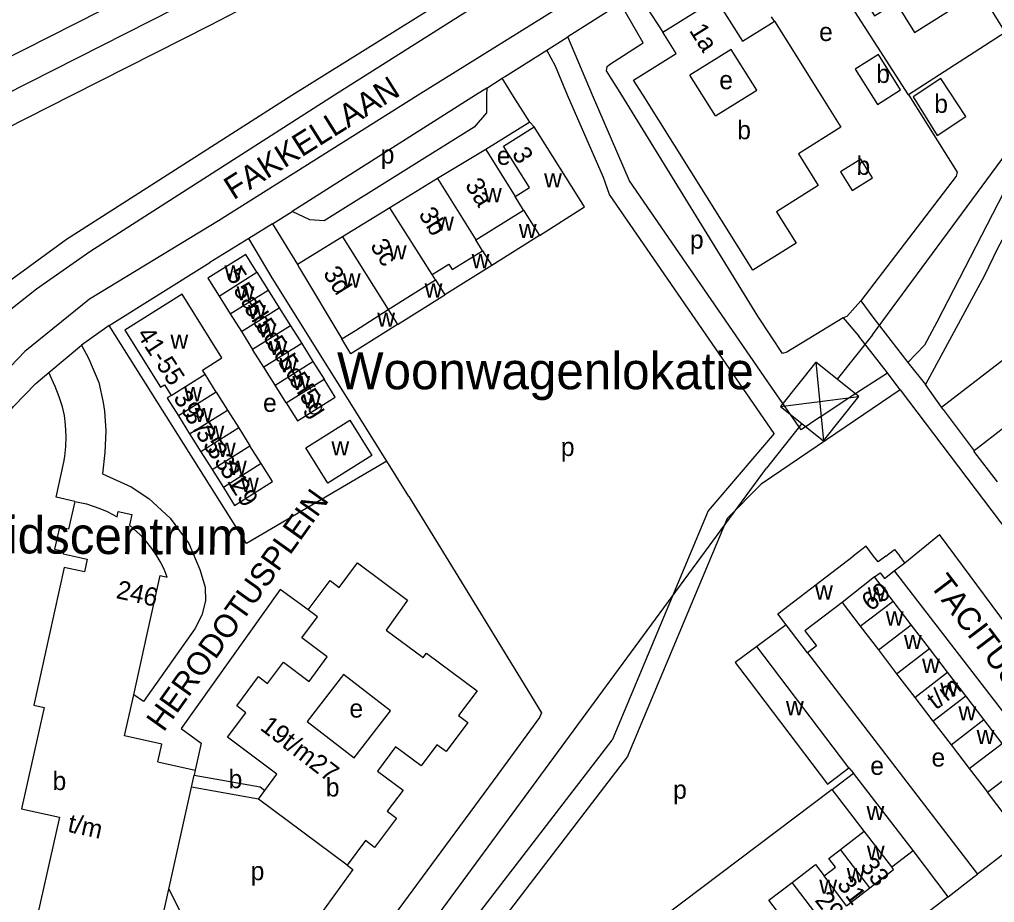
# Model space of a CAD drawing. Extents: x 158848 to 160613, y 385889 to 387762.
# Drawn here: x 159660 to 159871.5, y 386924.8 to 387116.4 of the extents above; entities that cross this region are included whole.
import ezdxf

# ---------------------------------------------------------------- set-up
doc = ezdxf.new("R2010")
doc.units = 0
for name, color, linetype in [('BLT_Basislijn', 7, 'Continuous'), ('BLT_Bebouwing', 7, 'Continuous'), ('BLT_Bebouwing_beschrifting', 7, 'Continuous'), ('BLT_Centroide', 7, 'Continuous'), ('BLT_Hoogspanningsmast_en_leidingen', 7, 'Continuous'), ('BLT_Huisnummer', 7, 'Continuous'), ('BLT_Huisnummer_ tussenligend', 7, 'Continuous'), ('BLT_Huisnummer_reeks', 7, 'Continuous'), ('BLT_Onderdoorgang_en_onderverdeling', 7, 'Continuous'), ('BLT_Onderverdeling_panden', 7, 'Continuous'), ('BLT_Straatnaam', 7, 'Continuous'), ('BLT_Terrein_beschrifting', 7, 'Continuous')]:
    doc.layers.add(name, color=color, linetype=linetype)

msp = doc.modelspace()

# ---------------------------------------------------------------- linework, layer by layer
at = {"layer": 'BLT_Basislijn'}
for p, q in [((159852.89, 387100.09), (159825.6, 387142.4)), ((159712.26, 387135.93), (159645.73, 387102.09)), ((159793.99, 387122.27), (159799.55, 387113.71)), ((159790.39, 387119.92), (159778.96, 387112.63)), ((159823.79, 387116.06), (159823.15, 387117.04)), ((159774.45, 387109.79), (159778.96, 387112.63)), ((159765.24, 387103.99), (159774.45, 387109.79)), ((159764.75, 387103.67), (159765.24, 387103.99)), ((159761.41, 387101.56), (159764.75, 387103.67)), ((159860.03, 387032.3), (159948.85, 387100.76)), ((159770.74, 387094.18), (159761.16, 387088.19)), ((159771.67, 387093.14), (159770.74, 387094.18)), ((159761.16, 387088.19), (159750.72, 387081.9)), ((159761.16, 387088.19), (159767.57, 387078.01)), ((159750.72, 387081.9), (159740.39, 387075.56)), ((159750.72, 387081.9), (159759, 387068.61)), ((159714.94, 387072.09), (159719.21, 387074.74)), ((159740.39, 387075.56), (159730.07, 387069.24)), ((159749.57, 387061.1), (159740.39, 387075.56)), ((159714.94, 387072.09), (159709.75, 387068.91)), ((159714.94, 387072.09), (159720.3, 387063.25)), ((159709.75, 387068.91), (159701.35, 387063.73)), ((159714.86, 387060.35), (159709.75, 387068.91)), ((159730.07, 387069.24), (159720.3, 387063.25)), ((159730.07, 387069.24), (159740.02, 387053.5)), ((159679.48, 387050.06), (159701.35, 387063.73)), ((159720.3, 387063.25), (159720.77, 387062.48)), ((159720.77, 387062.48), (159729.93, 387047.15)), ((159739.73, 387020.59), (159714.86, 387060.35)), ((159842.56, 387055.35), (159845.32, 387051.54)), ((159838.67, 387051.69), (159842.07, 387047.7)), ((159845.32, 387051.54), (159852.75, 387041.99)), ((159679.48, 387050.06), (159673.48, 387045.79)), ((159848.29, 387039.75), (159842.07, 387047.7)), ((159852.75, 387041.99), (159856.52, 387037.21)), ((159851.06, 387036.1), (159848.29, 387039.75)), ((159829.55, 387027.36), (159823.15, 387036.66)), ((159851.06, 387036.1), (159823.15, 387017.12)), ((159851.06, 387036.1), (159877.63, 387000.96)), ((159860.03, 387032.3), (159856.52, 387037.21)), ((159860.38, 387031.82), (159860.03, 387032.3)), ((159860.38, 387031.82), (159867.1, 387022.85)), ((159833.61, 387030.17), (159829.55, 387027.36)), ((159744.51, 387012.95), (159739.73, 387020.59)), ((159744.51, 387012.95), (159753.13, 386998.85)), ((159852.08, 386998.53), (159859.57, 387004.69)), ((159753.13, 386998.85), (159761.37, 386985.36)), ((159849.79, 386996.78), (159888.25, 386946.8)), ((159761.37, 386985.36), (159762.96, 386982.75)), ((159826.35, 386985.09), (159819.96, 386980.42)), ((159830.99, 386979.03), (159867.81, 386931)), ((159839.95, 386954.06), (159840.95, 386952.9)), ((159888.25, 386946.8), (159867.81, 386931)), ((159861.44, 386926.05), (159853.86, 386936.11)), ((159692.41, 386927.7), (159709.34, 386894.68))]:
    msp.add_line(p, q, dxfattribs=at)
for points in [[(159910.62, 387195.56), (159926.67, 387162.23), (159927.14, 387160.7), (159900.93, 387130.86), (159900.07, 387130.23), (159884.36, 387100), (159859.01, 387050.73), (159856.32, 387045.74), (159852.75, 387041.99)], [(159823.15, 387177.85), (159809.32, 387170.86), (159746.21, 387138.49), (159701.32, 387115.11), (159671.47, 387100), (159559.25, 387043.07), (159557.97, 387041.11), (159558.04, 387038.5), (159580.37, 386992.95), (159585.56, 386982.75)], [(159623.71, 387015.42), (159631.38, 387030.86), (159637.32, 387039.39), (159645.79, 387049.2), (159657.37, 387059.37), (159670.23, 387068.78), (159719.14, 387100), (159823.15, 387164.91)], [(159823.15, 387159.28), (159773.42, 387128.16), (159760.94, 387120.62), (159728.37, 387100), (159675.31, 387066.01), (159663.73, 387057.91), (159654.6, 387050.75), (159646.07, 387041.94), (159637.74, 387030.32), (159619.36, 386994.41)], [(159945.27, 387143.28), (159931.76, 387155.39), (159930.71, 387156.05), (159923.76, 387148.68), (159904.06, 387126.47), (159890.19, 387100), (159872.2, 387066.71), (159869.35, 387060.89), (159856.52, 387037.21)], [(159823.15, 387147.72), (159746.52, 387100), (159703.19, 387072.74), (159675.19, 387055.74), (159661.19, 387044.39), (159651.8, 387034.62), (159642.89, 387021.89), (159640.19, 387017.12), (159625.68, 386986.72)], [(159715.29, 387129.57), (159698.9, 387121.52), (159656.71, 387100), (159649.19, 387096.1)], [(159868.37, 387122.56), (159873.87, 387113.59), (159852.89, 387100.09)], [(159823.15, 387047.57), (159820.21, 387052.05), (159790.68, 387100), (159787.37, 387105.28), (159787.5, 387106.21), (159788.04, 387106.69), (159795.3, 387111.34), (159790.39, 387119.92)], [(159823.15, 387036.66), (159792.37, 387081.45), (159784.33, 387100), (159778.96, 387112.63)], [(159823.76, 387026.61), (159787.99, 387078.48), (159786.68, 387082.11), (159778.92, 387100), (159776.29, 387106.32), (159774.45, 387109.79)], [(159770.74, 387094.18), (159767.17, 387099.69), (159764.75, 387103.67)], [(159761.41, 387101.56), (159758.95, 387100), (159719.21, 387074.74)], [(159761.41, 387101.56), (159761.35, 387100), (159761.31, 387096.17), (159758.69, 387093.1), (159726.09, 387072.77), (159723, 387072.96), (159719.21, 387074.74)], [(159852.89, 387100.09), (159852.94, 387100), (159863.41, 387083.3), (159863.2, 387082.45), (159842.56, 387055.35)], [(159842.56, 387055.35), (159839.46, 387051.95), (159838.67, 387051.69)], [(159838.67, 387051.69), (159826.47, 387044.23), (159825.52, 387043.97), (159823.15, 387047.57)], [(159739.73, 387020.59), (159709.25, 387002.72), (159679.48, 387050.06)], [(159666.38, 387039.82), (159673.48, 387045.79)], [(159673.48, 387045.79), (159675.01, 387042.97), (159677.23, 387037.69), (159678.18, 387033.36), (159678.48, 387031.47), (159678.76, 387027.2), (159678.51, 387022.48), (159678.04, 387017.84), (159684.23, 387015.05), (159688.08, 387012.49), (159692.71, 387008.24), (159696.75, 387002.75), (159699.16, 386997.08), (159700.33, 386993.29), (159700.36, 386990.32), (159699.59, 386987.19), (159698.05, 386984.22), (159686.94, 386968.43), (159684.82, 386969.9)], [(159653.09, 387025.66), (159658.73, 387032.44), (159663.57, 387037.48), (159666.38, 387039.82)], [(159672.01, 387011.87), (159667.96, 387012.76), (159669.64, 387020.37), (159669.89, 387021.64), (159670.11, 387023.79), (159670.14, 387025.98), (159670.01, 387028.45), (159669.76, 387030.51), (159669.34, 387032.38), (159668.63, 387034.54), (159667.75, 387036.8), (159666.38, 387039.82)], [(159833.61, 387030.17), (159840.42, 387034.7), (159848.29, 387039.75)], [(159823.76, 387026.61), (159809.44, 387009.83), (159788.61, 386960.07)], [(159823.15, 387017.12), (159820.91, 387015.59), (159813.5, 387008.13)], [(159813.5, 387008.13), (159792.21, 386957.27), (159791.91, 386956.54), (159735.96, 386883.49), (159761.48, 386849.27)], [(159876.25, 386986.01), (159874.33, 386984.83), (159859.57, 387004.69)], [(159722.66, 386988.31), (159716.6, 386992.73), (159695.07, 386962.61), (159699.41, 386959.42), (159698.13, 386953.55)], [(159762.96, 386982.75), (159773.23, 386965.96), (159772.86, 386965), (159763.8, 386952.59), (159718.62, 386891.3)], [(159758.29, 386846.68), (159730.2, 386884.11), (159788.61, 386960.07)], [(159836.33, 386949.34), (159747.41, 386882.22), (159747.57, 386881.65), (159752.07, 386875.69)], [(159731.11, 386932.94), (159732.36, 386932.01), (159709.77, 386900.75), (159713.47, 386898.08)], [(159861.44, 386926.05), (159867.07, 386930.43), (159867.81, 386931)], [(159861.44, 386926.05), (159860.61, 386925.4), (159768.29, 386854.43)]]:
    msp.add_lwpolyline(points, dxfattribs=at)
at = {"layer": 'BLT_Bebouwing'}
for p, q in [((159823.15, 387115.66), (159823.79, 387116.06)), ((159814.4, 387109.92), (159805.44, 387104.35)), ((159765.05, 387088.96), (159771.67, 387093.14)), ((159782.6, 387075.78), (159771.67, 387093.14)), ((159770.69, 387079.98), (159765.05, 387088.96)), ((159767.57, 387078.01), (159770.69, 387079.98)), ((159769.34, 387075.06), (159767.57, 387078.01)), ((159759, 387068.61), (159769.34, 387075.06)), ((159772.84, 387069.55), (159782.6, 387075.78)), ((159760.47, 387066.26), (159759, 387068.61)), ((159772.84, 387069.55), (159762.48, 387063.06)), ((159711.53, 387061.59), (159713.96, 387057.72)), ((159762.48, 387063.06), (159752.32, 387056.7)), ((159740.02, 387053.5), (159750.27, 387059.95)), ((159750.27, 387059.95), (159749.57, 387061.1)), ((159713.96, 387057.72), (159716.39, 387053.85)), ((159703.31, 387056.43), (159705.74, 387052.56)), ((159742.03, 387050.25), (159752.32, 387056.7)), ((159716.39, 387053.85), (159718.82, 387049.98)), ((159705.74, 387052.56), (159708.17, 387048.7)), ((159708.17, 387048.7), (159710.6, 387044.83)), ((159718.82, 387049.98), (159721.24, 387046.11)), ((159713.03, 387040.96), (159710.6, 387044.83)), ((159721.24, 387046.11), (159723.68, 387042.24)), ((159715.46, 387037.09), (159713.03, 387040.96)), ((159723.68, 387042.24), (159726.1, 387038.38)), ((159702.71, 387035.57), (159700.28, 387039.46)), ((159717.89, 387033.22), (159715.46, 387037.09)), ((159702.71, 387035.57), (159705.15, 387031.69)), ((159694.49, 387030.41), (159696.93, 387026.53)), ((159705.15, 387031.69), (159707.59, 387027.8)), ((159707.59, 387027.8), (159710.02, 387023.92)), ((159873.87, 387028.04), (159867.1, 387022.85)), ((159712.43, 387020.07), (159710.02, 387023.92)), ((159699.38, 387022.64), (159701.82, 387018.76)), ((159701.82, 387018.76), (159704.26, 387014.88)), ((159849.79, 386996.78), (159852.08, 386998.53)), ((159852.08, 386998.53), (159850.96, 387000)), ((159849.52, 386990.25), (159845.52, 386995.48)), ((159838.45, 386989.93), (159842.39, 386984.79)), ((159853.46, 386985.1), (159849.52, 386990.25)), ((159830.99, 386979.03), (159826.35, 386985.09)), ((159842.39, 386984.79), (159846.33, 386979.64)), ((159857.41, 386979.96), (159853.46, 386985.1)), ((159839.95, 386954.06), (159819.96, 386980.42)), ((159846.33, 386979.64), (159850.27, 386974.49)), ((159861.35, 386974.81), (159857.41, 386979.96)), ((159865.29, 386969.66), (159861.35, 386974.81)), ((159730.28, 386974.28), (159722.41, 386964.08)), ((159740.48, 386966.41), (159730.28, 386974.28)), ((159850.27, 386974.49), (159854.22, 386969.35)), ((159854.22, 386969.35), (159858.16, 386964.2)), ((159869.23, 386964.52), (159865.29, 386969.66)), ((159732.61, 386956.22), (159740.48, 386966.41)), ((159858.16, 386964.2), (159862.1, 386959.05)), ((159873.17, 386959.37), (159869.23, 386964.52)), ((159722.41, 386964.08), (159732.61, 386956.22)), ((159862.1, 386959.05), (159866.04, 386953.91)), ((159853.86, 386936.11), (159840.95, 386952.9)), ((159843.26, 386940.33), (159836.33, 386949.34)), ((159849.23, 386932.55), (159853.86, 386936.11)), ((159839.45, 386924.15), (159844.5, 386928.03))]:
    msp.add_line(p, q, dxfattribs=at)
for points in [[(159843.38, 387130.8), (159845.13, 387127.97), (159840.59, 387125.12), (159845.52, 387117.21), (159850.12, 387120.08), (159854.18, 387113.62), (159868.37, 387122.56)], [(159799.55, 387113.71), (159811.09, 387120.94), (159816.87, 387111.72), (159823.15, 387115.66)], [(159823.79, 387116.06), (159826.45, 387111.82), (159833.85, 387100), (159838.21, 387093.04), (159828.99, 387087.26), (159833.3, 387080.38), (159824.24, 387074.71), (159828.5, 387067.91), (159823.32, 387064.67), (159823.15, 387064.56)], [(159823.15, 387064.56), (159819.08, 387062.01), (159795.28, 387100), (159793.23, 387103.27), (159802.47, 387109.05), (159799.55, 387113.71)], [(159810.97, 387095.52), (159819.96, 387101.1), (159814.4, 387109.92)], [(159810.97, 387095.52), (159805.44, 387104.35)], [(159838.09, 387083.38), (159840.65, 387079.3), (159845.08, 387082.08), (159842.52, 387086.15), (159838.09, 387083.38)], [(159749.57, 387061.1), (159753.17, 387063.35), (159753.92, 387062.16), (159760.47, 387066.26)], [(159711.53, 387061.59), (159709.1, 387065.46), (159700.89, 387060.3), (159703.31, 387056.43)], [(159700.28, 387039.46), (159699.71, 387040.37), (159703.91, 387043.03), (159695.3, 387056.8), (159682.85, 387048.99), (159690.62, 387036.62), (159691.49, 387037.18), (159691.49, 387037.18), (159692.95, 387034.86)], [(159729.93, 387047.15), (159732.88, 387048.98), (159740.02, 387053.5)], [(159742.03, 387050.25), (159731.93, 387043.92), (159729.93, 387047.15)], [(159717.89, 387033.22), (159720.32, 387029.35), (159728.53, 387034.51), (159726.1, 387038.38)], [(159692.95, 387034.86), (159692.06, 387034.3), (159694.49, 387030.41)], [(159696.93, 387026.53), (159696.93, 387026.53), (159699.38, 387022.64)], [(159867.1, 387022.85), (159867, 387022.77), (159872.1, 387016.13)], [(159704.26, 387014.88), (159706.7, 387010.99), (159714.89, 387016.15), (159712.43, 387020.07)], [(159672.01, 387011.87), (159670.67, 387005.81), (159668.7, 387006.24), (159667.64, 387001.48), (159669.62, 387001.06), (159669.49, 387000.51), (159674.71, 386999.37)], [(159672.01, 387011.87), (159674.54, 387011.31), (159677.46, 387010.35), (159679.02, 387009.67), (159681.21, 387008.53)], [(159681.21, 387008.53), (159681.45, 387009.68), (159684.4, 387009.03), (159683.87, 387006.69)], [(159690.56, 386995.8), (159692.1, 386995.46), (159691.42, 386997.13), (159690.57, 386998.82), (159689.85, 387000.03), (159688.76, 387001.68), (159687.36, 387003.39), (159686.24, 387004.59), (159683.87, 387006.69)], [(159845.28, 387000), (159843.66, 387002.12), (159840.9, 387000)], [(159847.93, 387000), (159849.84, 387001.46), (159850.96, 387000)], [(159674.71, 386999.37), (159674.16, 386996.57), (159669.71, 386997.5), (159666.47, 386982.78)], [(159727.39, 386994.67), (159729.37, 386993.2), (159733.35, 386998.51)], [(159733.35, 386998.51), (159744.21, 386990.44), (159739.59, 386983.96)], [(159826.35, 386985.09), (159824.53, 386987.47), (159840.9, 387000)], [(159847.93, 387000), (159846.26, 386998.72), (159845.28, 387000)], [(159845.52, 386995.48), (159846.7, 386996.38), (159847.65, 386995.14), (159849.79, 386996.78)], [(159687.67, 386982.75), (159690.56, 386995.8)], [(159722.66, 386988.31), (159727.39, 386994.67)], [(159838.45, 386989.93), (159830.41, 386983.77), (159832.91, 386980.5), (159830.99, 386979.03)], [(159724.67, 386986.8), (159722.66, 386988.31)], [(159726.79, 386978.14), (159721.26, 386982.24), (159724.67, 386986.8)], [(159739.59, 386983.96), (159747.59, 386978), (159748.3, 386978.95)], [(159666.47, 386982.78), (159663.11, 386967.63), (159665.4, 386967.12), (159660.47, 386945.2)], [(159684.82, 386969.9), (159687.67, 386982.75)], [(159748.3, 386978.95), (159759.29, 386970.76), (159755.28, 386965.45), (159757.28, 386963.93), (159752.55, 386957.57), (159750.59, 386959.05), (159747.16, 386954.51), (159741.61, 386958.62), (159737.66, 386953.35), (159743.23, 386949.21), (159739.81, 386944.63), (159741.8, 386943.15), (159737.05, 386936.79)], [(159819.96, 386980.42), (159815.3, 386976.88), (159818.32, 386972.9), (159835.3, 386950.53), (159835.97, 386951.04), (159839.95, 386954.06)], [(159711.89, 386973.86), (159713.86, 386972.39), (159717.3, 386976.96)], [(159717.3, 386976.96), (159722.86, 386972.82), (159726.79, 386978.14)], [(159709.14, 386966.02), (159707.16, 386967.5), (159711.89, 386973.86)], [(159690.07, 386955.35), (159690.91, 386959.2), (159682.84, 386960.99), (159684.82, 386969.9)], [(159715.86, 386952.71), (159705.17, 386960.7), (159709.14, 386966.02)], [(159690.07, 386955.35), (159698.13, 386953.55)], [(159698.13, 386953.55), (159697.89, 386952.49)], [(159866.04, 386953.91), (159869.99, 386948.76)], [(159877.12, 386954.22), (159881.18, 386948.92), (159874.04, 386943.46), (159869.99, 386948.76)], [(159697.89, 386952.49), (159712.24, 386949.93), (159713.23, 386949.17)], [(159713.23, 386949.17), (159715.86, 386952.71)], [(159836.33, 386949.34), (159836.99, 386949.85), (159840.95, 386952.9)], [(159692.41, 386927.7), (159697.31, 386949.86)], [(159711.88, 386947.25), (159697.31, 386949.86)], [(159731.11, 386932.94), (159711.88, 386947.25)], [(159660.47, 386945.2), (159668.68, 386943.37), (159662.54, 386916.04)], [(159838.15, 386936.33), (159843.26, 386940.33)], [(159737.05, 386936.79), (159735.06, 386938.28), (159731.11, 386932.94)], [(159834.57, 386930.63), (159837.02, 386932.51), (159835.59, 386934.37), (159838.15, 386936.33)], [(159827.6, 386929.2), (159832.71, 386933.1), (159834.57, 386930.63)], [(159844.5, 386928.03), (159849.64, 386931.99), (159849.23, 386932.55)], [(159824.46, 386922.86), (159822.57, 386925.36), (159827.6, 386929.2)], [(159682.97, 386885.03), (159692.41, 386927.7)]]:
    msp.add_lwpolyline(points, dxfattribs=at)
for points in [[(159846.34, 387108.84), (159841.31, 387105.68), (159846.14, 387097.98), (159851.16, 387101.15)], [(159859.86, 387103.61), (159853.87, 387099.63), (159859.12, 387091.27), (159865.32, 387095.39)], [(159722.14, 387023.46), (159731.7, 387029.48), (159736.46, 387021.8), (159726.9, 387015.82)]]:
    msp.add_lwpolyline(points, close=True, dxfattribs=at)
at = {"layer": 'BLT_Hoogspanningsmast_en_leidingen'}
for p, q in [((159845.08, 387048.01), (159951.04, 387192.01)), ((159845.08, 387048.01), (159837.42, 387038.38)), ((159832.75, 387042.09), (159834.42, 387025.02)), ((159825.08, 387032.45), (159842.09, 387034.66)), ((159829.75, 387028.74), (159823.15, 387020.44)), ((159795.4, 386982.75), (159822.09, 387019.1)), ((159823.15, 387020.44), (159822.09, 387019.1)), ((159713.86, 386871.84), (159795.4, 386982.75))]:
    msp.add_line(p, q, dxfattribs=at)
msp.add_lwpolyline([(159832.75, 387042.09), (159825.08, 387032.45), (159834.42, 387025.02), (159842.09, 387034.66)], close=True, dxfattribs=at)
at = {"layer": 'BLT_Onderdoorgang_en_onderverdeling'}
for p, q in [((159697.31, 386949.86), (159697.89, 386952.49)), ((159711.88, 386947.25), (159713.23, 386949.17))]:
    msp.add_line(p, q, dxfattribs=at)
at = {"layer": 'BLT_Onderverdeling_panden'}
for p, q in [((159769.34, 387075.06), (159772.84, 387069.55)), ((159760.47, 387066.26), (159762.48, 387063.06)), ((159703.31, 387056.43), (159711.53, 387061.59)), ((159750.27, 387059.95), (159752.32, 387056.7)), ((159705.74, 387052.56), (159713.96, 387057.72)), ((159708.17, 387048.7), (159716.39, 387053.85)), ((159740.02, 387053.5), (159742.03, 387050.25)), ((159718.82, 387049.98), (159710.6, 387044.83)), ((159721.24, 387046.11), (159713.03, 387040.96)), ((159715.46, 387037.09), (159723.68, 387042.24)), ((159692.95, 387034.86), (159700.28, 387039.46)), ((159717.89, 387033.22), (159726.1, 387038.38)), ((159702.71, 387035.57), (159694.49, 387030.41)), ((159696.93, 387026.53), (159705.15, 387031.69)), ((159707.59, 387027.8), (159699.38, 387022.64)), ((159701.82, 387018.76), (159710.02, 387023.92)), ((159712.43, 387020.07), (159704.26, 387014.88)), ((159845.52, 386995.48), (159838.45, 386989.93)), ((159842.39, 386984.79), (159849.52, 386990.25)), ((159846.33, 386979.64), (159853.46, 386985.1)), ((159850.27, 386974.49), (159857.41, 386979.96)), ((159854.22, 386969.35), (159861.35, 386974.81)), ((159858.16, 386964.2), (159865.29, 386969.66)), ((159862.1, 386959.05), (159869.23, 386964.52)), ((159866.04, 386953.91), (159873.17, 386959.37)), ((159869.99, 386948.76), (159877.12, 386954.22)), ((159849.23, 386932.55), (159843.26, 386940.33)), ((159844.5, 386928.03), (159838.15, 386936.33)), ((159839.45, 386924.15), (159834.57, 386930.63)), ((159834.4, 386920.28), (159827.6, 386929.2))]:
    msp.add_line(p, q, dxfattribs=at)

# ---------------------------------------------------------------- texts
at = {"layer": 'BLT_Bebouwing_beschrifting'}
msp.add_text('Gezondheidscentrum', height=7.9999, rotation=359.5665, dxfattribs=at).set_placement((159607.87, 387000.99))
at = {"layer": 'BLT_Centroide'}
for s, p in [('e', (159833.48, 387111.75)), ('b', (159845.87, 387102.66)), ('e', (159811.82, 387101.31)), ('b', (159858.46, 387096.16)), ('b', (159815.72, 387090.45)), ('p', (159738.38, 387085.17)), ('e', (159763.57, 387084.89)), ('b', (159841.59, 387082.72)), ('w', (159773.83, 387079.98)), ('w', (159760.78, 387076.78)), ('w', (159750.41, 387070.61)), ('w', (159768.34, 387069)), ('p', (159805.46, 387066.7)), ('w', (159740.14, 387064.36)), ('w', (159758.1, 387062.47)), ('w', (159704.5, 387059.99)), ('w', (159730.17, 387058.27)), ('w', (159707.12, 387055.49)), ('w', (159747.91, 387056.09)), ('w', (159709.62, 387051.44)), ('w', (159737.63, 387049.75)), ('w', (159711.87, 387047.44)), ('w', (159692.77, 387045)), ('w', (159714.24, 387043.63)), ('w', (159716.45, 387039.88)), ('w', (159719.22, 387036.03)), ('w', (159695.77, 387033.6)), ('e', (159712.86, 387031.29)), ('w', (159721.51, 387032.03)), ('w', (159698.06, 387029.06)), ('w', (159700.6, 387025.26)), ('w', (159703.07, 387021.53)), ('w', (159727.69, 387021.85)), ('p', (159777.46, 387021.71)), ('w', (159705.45, 387017.61)), ('w', (159708.07, 387013.94)), ('w', (159832.6, 386990.56)), ('w', (159844.04, 386990.12)), ('w', (159847.93, 386984.94)), ('w', (159851.88, 386979.81)), ('w', (159855.81, 386974.66)), ('w', (159859.75, 386969.5)), ('w', (159826.29, 386965.47)), ('e', (159731.6, 386964.96)), ('w', (159863.7, 386964.34)), ('w', (159867.64, 386959.22)), ('e', (159844.58, 386952.54)), ('e', (159857.85, 386954.33)), ('b', (159705.39, 386949.64)), ('b', (159667.2, 386949.22)), ('b', (159726.48, 386947.84)), ('p', (159801.81, 386947.36)), ('w', (159843.76, 386942.72)), ('w', (159843.83, 386934.12)), ('p', (159710.18, 386929.67)), ('w', (159839.47, 386929.23)), ('w', (159833.52, 386926.73))]:
    msp.add_text(s, height=4, dxfattribs=at).set_placement(p)
at = {"layer": 'BLT_Huisnummer'}
for s, rotation, p in [('1a', 302.0699, (159805.2, 387114.05)), ('3', 300.2437, (159766.74, 387087.33)), ('3a', 301.6784, (159756.56, 387080.49)), ('3b', 302.3035, (159746.47, 387074.16)), ('3c', 302.3035, (159735.98, 387067.31)), ('5', 303.2701, (159704.67, 387061.07)), ('3d', 302.0788, (159725.77, 387061.35)), ('5a', 303.2701, (159706.25, 387057.71)), ('5b', 303.2701, (159708.57, 387053.83)), ('5c', 303.2701, (159711.07, 387049.98)), ('5d', 303.2701, (159713.4, 387046.19)), ('5e', 303.2701, (159715.9, 387042.2)), ('5f', 303.2701, (159718.32, 387038.27)), ('5g', 303.0812, (159720.62, 387034.73)), ('39', 303.0287, (159693.27, 387034.33)), ('37', 303.0287, (159695.62, 387030.61)), ('33', 303.0287, (159700.52, 387023.08)), ('29', 303.0287, (159705.47, 387015.29)), ('33', 307.5407, (159842.21, 386932.7)), ('29', 307.5407, (159832.4, 386925.31))]:
    msp.add_text(s, height=4, rotation=rotation, dxfattribs=at).set_placement(p)
at = {"layer": 'BLT_Huisnummer_ tussenligend'}
for s, rotation, p in [('35', 303.0287, (159698.08, 387026.68)), ('31', 303.0287, (159703.33, 387018.78)), ('31', 307.5407, (159837.18, 386928.71))]:
    msp.add_text(s, height=4, rotation=rotation, dxfattribs=at).set_placement(p)
at = {"layer": 'BLT_Huisnummer_reeks'}
for s, rotation, p in [('41-55', 303.0287, (159685.34, 387048.12)), ('246', 347.5011, (159680.81, 386990.92)), ('69', 37.4841, (159844.64, 386987.88)), ('t/m', 37.4841, (159858.8, 386966.5)), ('19t/m27', 322.3519, (159712, 386962.49)), ('t/m', 347.5011, (159670.29, 386940.24))]:
    msp.add_text(s, height=4, rotation=rotation, dxfattribs=at).set_placement(p)
at = {"layer": 'BLT_Straatnaam'}
for s, rotation, p in [('FAKKELLAAN', 32.1774, (159706.45, 387077.17)), ('HERODOTUSPLEIN', 54.4772, (159691.28, 386961.65)), ('TACITUSLAAN', 307.2564, (159857.31, 386993.69))]:
    msp.add_text(s, height=5, rotation=rotation, dxfattribs=at).set_placement(p)
at = {"layer": 'BLT_Terrein_beschrifting'}
msp.add_text('Woonwagenlokatie', height=8, dxfattribs=at).set_placement((159728.91, 387036.2))

doc.saveas('drawing.dxf')
